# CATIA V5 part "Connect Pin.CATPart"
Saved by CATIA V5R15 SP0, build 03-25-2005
Part number: Connect Pin
Bounding box of the stored display mesh (mm): x -28.992 to 28.992, y -79 to 79, z -28.994 to 28.994
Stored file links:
  E:\#01 CATIA Lecture Materials\#06 DMU\#11 DMU Page01 KIN EX11\Connect Pin.CATPart
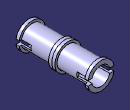
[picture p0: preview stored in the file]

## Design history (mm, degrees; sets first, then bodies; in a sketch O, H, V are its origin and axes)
Body1 (main body)
  Sketch1 on xy-plane, origin (0, 0, 0), H (1, 0, 0), V (0, 1, 0)
    point P1 (0, 79)
    line L1 (0, 79) -> (29, 79)
    line L2 (29, 79) -> (29, 72)
    line L3 (29, 72) -> (24, 72)
    point P4 (24, 72)
    line L4 (24, 72) -> (24, 7)
    point P5 (24, 7)
    line L5 (24, 7) -> (29, 7)
    point P6 (29, 7)
    line L6 (29, 7) -> (29, 0)
    point P7 (29, 0)
    point P9 (0, -79)
    line L7 (0, -79) -> (29, -79)
    line L8 (29, -79) -> (29, -72)
    point P11 (24, -72)
    line L9 (29, -72) -> (24, -72)
    point P12 (24, -7)
    line L10 (24, -72) -> (24, -7)
    point P13 (29, -7)
    line L11 (24, -7) -> (29, -7)
    point P14 (29, 0)
    line L12 (29, -7) -> (29, 0)
    axis line L13 (0, -92.0572) -> (0, 94.0849)
    point P15 (0, -92.0572)
    distance L1 H = 79
    length L2 = 7
    length L6 = 7
    distance L2 V = 29
    distance L4 V = 24
    distance L8 L13 = 29
    coincidence: P1 V, P6 L2, P7 H, P15 V, P7 P14
    horizontal: L1 H, L3 H, L5 H
    vertical: L2 V, L4 V, L6 V, L13 V
    symmetry: P1 P9 H, L1 L7 H, P4 P11 H, L3 L9 H, P5 P12 H, L4 L10 H, P6 P13 H, L5 L11 H, P7 P14 H, L6 L12 H
  Shaft1: profile Sketch1, axis Sketch1.L13, angle 360
  Sketch2 on face of Shaft1 from Sketch1.L7, origin (0, -79, 0), H (1, 0, 0), V (0, 0, 1)
    circle A1 centre (0, 0) radius 20
    radius A1 = 20
  Pocket1: profile Sketch2, direction (0, 1, 0), through (limit type 3)
  Sketch3 on yz-plane, origin (0, 0, 0), H (0, 1, 0), V (0, 0, 1)
    point P1 (50, 5)
    line L1 (50, 5) -> (79, 5)
    line L2 (79, 5) -> (79, -5)
    line L3 (79, -5) -> (50, -5)
    line L4 (50, -5) -> (50, 5)
    point P2 (79, 5)
    point P3 (79, -5)
    point P4 (50, -5)
    reference intersected line E1 (79, 29) -> (79, -29) from face of Shaft1 from Sketch1.L1
    point P5 (-50, 5)
    point P6 (-79, 5)
    point P7 (-79, -5)
    point P8 (-50, -5)
    line L5 (-50, 5) -> (-79, 5)
    line L6 (-79, 5) -> (-79, -5)
    line L7 (-79, -5) -> (-50, -5)
    line L8 (-50, -5) -> (-50, 5)
    distance L4 V = 50
    distance L3 L1 = 10
    horizontal: L1 H, L3 H
    vertical: L2 V, L4 V
    symmetry: L3 L1 H, P1 P5 V, P2 P6 V, P3 P7 V, P4 P8 V, L1 L5 V, L2 L6 V, L3 L7 V, L4 L8 V
    coincidence: L2 E1
  Pocket2: profile Sketch3, direction (-1, 0, 0), through (limit type 3), opposite side through (limit type 3)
